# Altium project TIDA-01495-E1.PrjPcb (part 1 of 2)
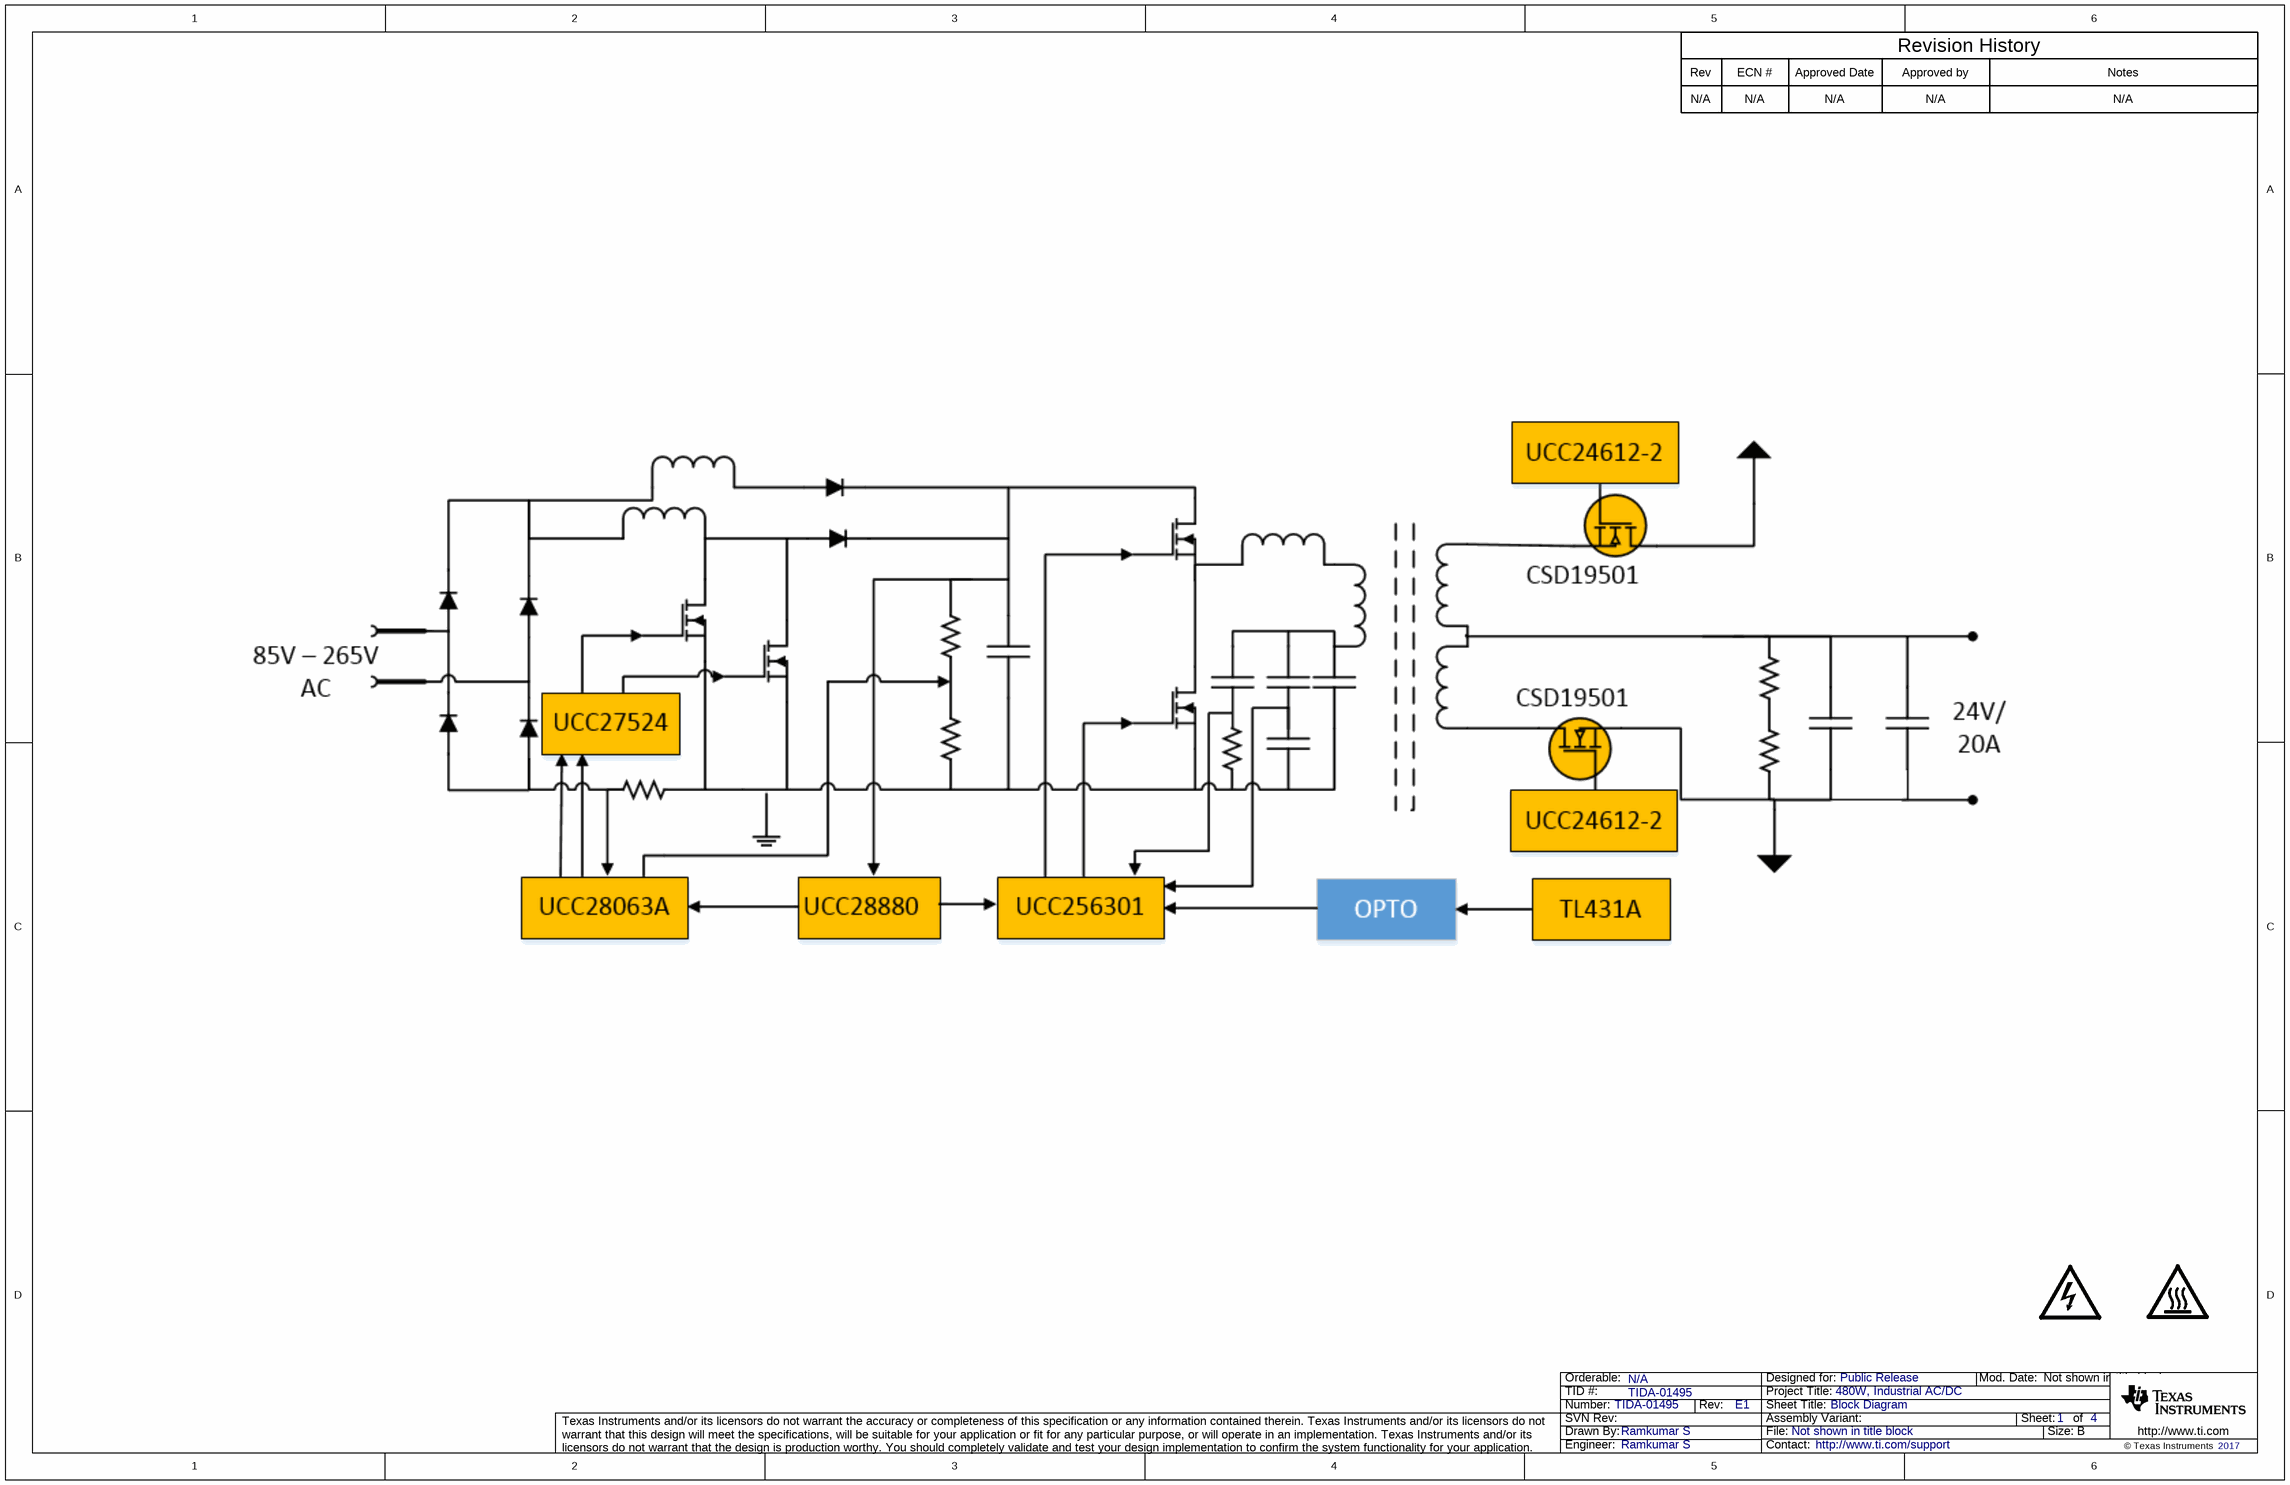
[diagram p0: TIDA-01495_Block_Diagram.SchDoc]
CopyrightYear: 2017; EVM_orderable: N/A; PCB_Layout: Akshay Labhe; PCB_Rev: E1; PRJ_Customer: Public Release; PRJ_Engineer: Ramkumar S; PRJ_Number: TIDA-01495; PRJ_Title: 480W, Industrial AC/DC; SCH_Rev: E1; TechSupport: http://www.ti.com/support; TID: TIDA-01495
4 sheets, 249 parts. Net scope: global (net labels, ports and power ports of the same name join across sheets).
Board file: TIDA-01495_PCB.PcbDoc
Sheets:
  TIDA-01495_Block_Diagram.SchDoc
  TIDA-01495_PFC.SchDoc
  TIDA-01495-LLC.SchDoc
  TIDA-01495_Hardware.SchDoc

## Sheet TIDA-01495_Block_Diagram.SchDoc: Block Diagram
size 431 x 279 mm; Date: Not shown in title block; ApprovedBy: Not shown in title block; CheckedBy: Not shown in title block; Author: Not shown in title block; CompanyName: Not shown in title block; DrawnBy: Ramkumar S; Engineer: Ramkumar S; Organization: Not shown in title block; Address1: Not shown in title block; Address2: Not shown in title block; Address3: Not shown in title block; Address4: Not shown in title block; DocumentNumber: 1; Revision: Use project parameter SCH_Rev; SheetNumber: 1; SheetTotal: 4; PageSetup: Record=PageOptions¦CenterHorizontal=True¦CenterVertical=True¦PrintScale=1.00¦XCorrection=1.00¦YCorrection=1.00¦PrintKind=0¦BorderSize=5000000¦LeftOffset=0¦BottomOffset=0¦Orientation=2¦PaperLength=1000¦PaperWidth=1000¦Scale=100¦PaperSource=15¦PrintQuality=600¦MediaType=1¦DitherType=10¦PaperKind=Letter¦PrintScaleMode=1

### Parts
(Parts that share a designator on the sheet are numbered #1, #2 ... from top to bottom, then left to right.)
LOGO?#1  DANGER HIGH VOLTAGE  [IEC_HighVoltage_Small]  (value not drawn)  (graphical)
LOGO?#2  CAUTION HOT SURFACE  [IEC_HotSurface_Small]  (value not drawn)  (graphical)

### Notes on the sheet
- Rev
- N/A
- ECN #
- Approved Date
- Approved by
- Revision History
- Notes

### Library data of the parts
LOGO?#1 = IEC_HighVoltage: IEC 61010-1 High Voltage Warning; SymbolCreator: a0412235
LOGO?#2 = IEC_HotSurface: IEC 61010-1 Hot Surface Warning; SymbolCreator: a0412235

## Sheet TIDA-01495_PFC.SchDoc: PFC
size 431 x 279 mm; Date: Not shown in title block; ApprovedBy: Not shown in title block; CheckedBy: Not shown in title block; Author: Not shown in title block; CompanyName: Not shown in title block; DrawnBy: Ramkumar S; Engineer: Ramkumar S; Organization: Not shown in title block; Address1: Not shown in title block; Address2: Not shown in title block; Address3: Not shown in title block; Address4: Not shown in title block; DocumentNumber: 1; Revision: Use project parameter SCH_Rev; SheetNumber: 2; SheetTotal: 4; PageSetup: Record=PageOptions¦CenterHorizontal=True¦CenterVertical=True¦PrintScale=1.00¦XCorrection=1.00¦YCorrection=1.00¦PrintKind=0¦BorderSize=5000000¦LeftOffset=0¦BottomOffset=0¦Orientation=2¦PaperLength=1000¦PaperWidth=1000¦Scale=100¦PaperSource=15¦PrintQuality=600¦MediaType=1¦DitherType=10¦PaperKind=Letter¦PrintScaleMode=1
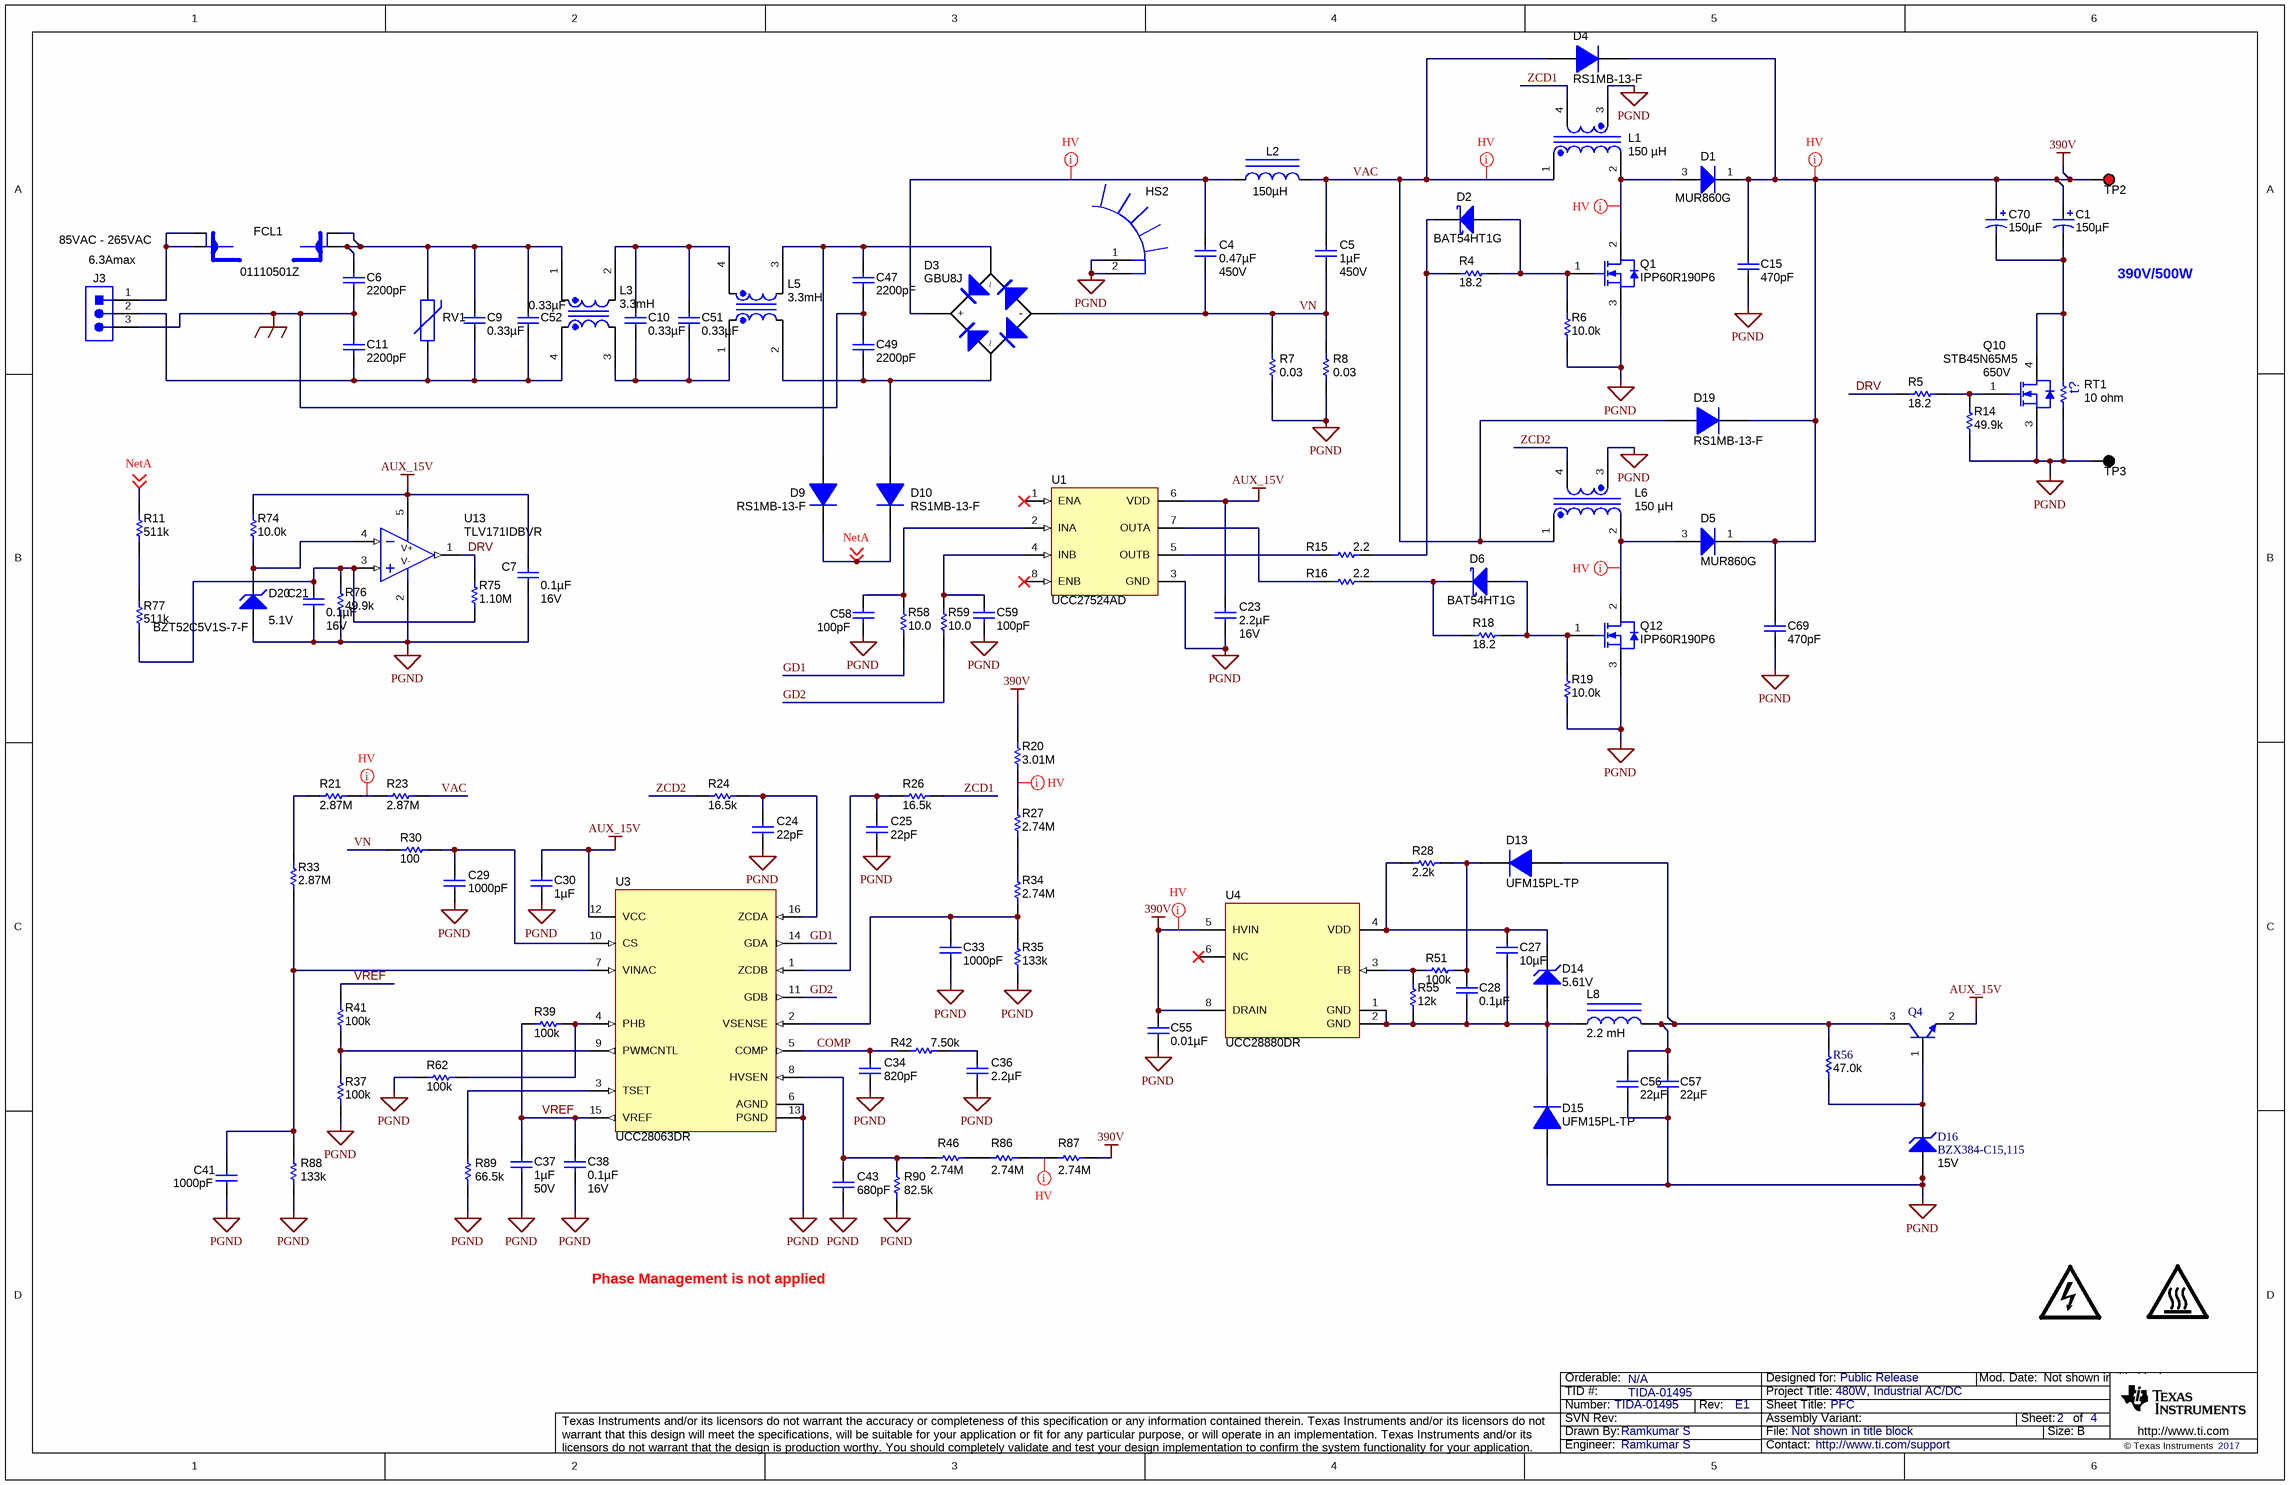
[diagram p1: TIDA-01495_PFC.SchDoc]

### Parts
(Parts that share a designator on the sheet are numbered #1, #2 ... from top to bottom, then left to right.)
C1  ValueDisplayed: 150µF  [KXG_1800x4000_horizontalDown]  (hidden comment: 450BXW150MEFC18X45)
C4  ValueDisplayed: 0.47µF  Value2: 450V  [MPK_1800x650]  (hidden comment: 450MPK474J)
C5  ValueDisplayed: 1µF  Value2: 450V  [MPK_1800x950]  (hidden comment: 450MPK105J)
C6  ValueDisplayed: 2200pF  [CD45_700x600x1100]  (hidden comment: AY2222M35Y5US63L7)
C7  ValueDisplayed: 0.1µF  Value2: 16V  [0603]  (hidden comment: EMK107B7104KA-T)
C9  ValueDisplayed: 0.33µF  [B32922_14.5mm]  (hidden comment: B32922C3334K)
C10  ValueDisplayed: 0.33µF  [B32922_14.5mm]  (hidden comment: B32922C3334K)
C11  ValueDisplayed: 2200pF  [CD45_700x600x1100]  (hidden comment: AY2222M35Y5US63L7)
C15  ValueDisplayed: 470pF  [1210]  (hidden comment: VJ1210Y471KXEAT5Z)
C21  ValueDisplayed: 0.1µF  Value2: 16V  [0603]  (hidden comment: EMK107B7104KA-T)
C23  ValueDisplayed: 2.2µF  Value2: 16V  [0805_HV]  (hidden comment: 0805YD225KAT2A)
C24  ValueDisplayed: 22pF  [0603]  (hidden comment: C0603C220J5GACTU)
C25  ValueDisplayed: 22pF  [0603]  (hidden comment: C0603C220J5GACTU)
C27  ValueDisplayed: 10µF  [0603]  (hidden comment: C1608X5R1A106M)
C28  ValueDisplayed: 0.1µF  [0603]  (hidden comment: 0603YC104JAT2A)
C29  ValueDisplayed: 1000pF  [0603]  (hidden comment: C1608X7R1H102K)
C30  ValueDisplayed: 1µF  [0603]  (hidden comment: GRM188R71E105KA12D)
C33  ValueDisplayed: 1000pF  [0603]  (hidden comment: C1608X7R1H102K)
C34  ValueDisplayed: 820pF  [0603]  (hidden comment: 06035A821JAT2A)
C36  ValueDisplayed: 2.2µF  [0805_HV]  (hidden comment: 0805YD225KAT2A)
C37  ValueDisplayed: 1µF  Value2: 50V  [0603]  (hidden comment: UMK107AB7105KA-T)
C38  ValueDisplayed: 0.1µF  Value2: 16V  [0603]  (hidden comment: EMK107B7104KA-T)
C41  ValueDisplayed: 1000pF  [0603]  (hidden comment: 06031C102MAT2A)
C43  ValueDisplayed: 680pF  [0603]  (hidden comment: GRM188R71H681KA01D)
C47  ValueDisplayed: 2200pF  [CAPRD500W60D800H850]  (hidden comment: DE2E3KY222MA2BM01)
C49  ValueDisplayed: 2200pF  [CAPRD500W60D800H850]  (hidden comment: DE2E3KY222MA2BM01)
C51  ValueDisplayed: 0.33µF  [B32922_14.5mm]  (hidden comment: B32922C3334K)
C52  ValueDisplayed: 0.33µF  [B32922_14.5mm]  (hidden comment: B32922C3334K)
C55  ValueDisplayed: 0.01µF  [1808]  (hidden comment: VJ1808Y103KBLAT4X)
C56  ValueDisplayed: 22µF  [1206_180]  (hidden comment: C3216X5R1V226M160AC)
C57  ValueDisplayed: 22µF  [1206_180]  (hidden comment: C3216X5R1V226M160AC)
C58  ValueDisplayed: 100pF  [0805_HV1]  (hidden comment: 08055A101JAT2A)
C59  ValueDisplayed: 100pF  [0805_HV1]  (hidden comment: 08055A101JAT2A)
C69  ValueDisplayed: 470pF  [1210]  (hidden comment: VJ1210Y471KXEAT5Z)
C70  ValueDisplayed: 150µF  [KXG_1800x4000_horizontalDown]  (hidden comment: 450BXW150MEFC18X45)
D1  MUR860G  [TO-220AC_HORIZ]
D2  BAT54HT1G  [sod-323]
D3  GBU8J  [GBU]
D4  RS1MB-13-F  [SMB]
D5  MUR860G  [TO-220AC_HORIZ]
D6  BAT54HT1G  [sod-323]
D9  RS1MB-13-F  [SMB]
D10  RS1MB-13-F  [SMB]
D13  UFM15PL-TP  [SOD-123FL]
D14  5.61V  [SOD-523]
D15  UFM15PL-TP  [SOD-123FL]
D16  BZX384-C15,115  value 15V  [sod-323]
D19  RS1MB-13-F  [SMB]
D20  BZT52C5V1S-7-F  value 5.1V  [SOD-323]
FCL1  01110501Z  [LITTELFUSE_01110501Z]
HS2  (no value)  [HEATSINK_782653B04250G - duplicate1]
J3  350429-1  [TE_350429-1]  (value not drawn)
L1  value 150 µH  [WE-CMBH_Updated]  (hidden comment: Custom)
L2  ValueDisplayed: 150µH  [IND_7447020]  (hidden comment: 7447076)
L3  ValueDisplayed: 3.3mH  [WE-CMBH]  (hidden comment: 744834433)
L5  ValueDisplayed: 3.3mH  [WE-CMBH]  (hidden comment: 744834433)
L6  value 150 µH  [WE-CMBH_Updated]  (hidden comment: Custom)
L8  ValueDisplayed: 2.2 mH  [WE-TI_5075]  (hidden comment: 744741222)
LOGO?#3  DANGER HIGH VOLTAGE  [IEC_HighVoltage_Small]  (value not drawn)  (graphical)
LOGO?#4  CAUTION HOT SURFACE  [IEC_HotSurface_Small]  (value not drawn)  (graphical)
Q1  IPP60R190P6  [TO-220AB_HORIZONTAL]
Q4  BC848CLT1G  [SOT-23]  (value not drawn)
Q10  STB45N65M5  value 650V  [DDPAK]
Q12  IPP60R190P6  [TO-220AB_HORIZONTAL]
R4  ValueDisplayed: 18.2  [0805_HV1]  (hidden comment: CRCW080518R2FKEA)
R5  ValueDisplayed: 18.2  [0805_HV1]  (hidden comment: CRCW080518R2FKEA)
R6  ValueDisplayed: 10.0k  [0805_HV]  (hidden comment: CRCW080510K0FKEA)
R7  ValueDisplayed: 0.03  [2512]  (hidden comment: CSRN2512FK30L0)
R8  ValueDisplayed: 0.03  [2512]  (hidden comment: CSRN2512FK30L0)
R11  value 511k  [1206]  (hidden comment: CRCW1206511KFKEA)
R14  value 49.9k  [1206]  (hidden comment: CRCW120649K9FKEA)
R15  ValueDisplayed: 2.2  [0805_HV1]  (hidden comment: CRCW08052R20JNEA)
R16  ValueDisplayed: 2.2  [0805_HV1]  (hidden comment: CRCW08052R20JNEA)
R18  ValueDisplayed: 18.2  [0805_HV1]  (hidden comment: CRCW080518R2FKEA)
R19  ValueDisplayed: 10.0k  [0805_HV]  (hidden comment: CRCW080510K0FKEA)
R20  ValueDisplayed: 3.01M  [0805_HV]  (hidden comment: CRCW08053M01FKEA)
R21  ValueDisplayed: 2.87M  [0805_HV]  (hidden comment: CRCW08052M87FKEA)
R23  ValueDisplayed: 2.87M  [0805_HV]  (hidden comment: CRCW08052M87FKEA)
R24  ValueDisplayed: 16.5k  [0603]  (hidden comment: CRCW060316K5FKEA)
R26  ValueDisplayed: 16.5k  [0603]  (hidden comment: CRCW060316K5FKEA)
R27  ValueDisplayed: 2.74M  [0805_HV]  (hidden comment: CRCW08052M74FKEA)
R28  ValueDisplayed: 2.2k  [0603]  (hidden comment: CRCW06032K20JNEA)
R30  ValueDisplayed: 100  [0603]  (hidden comment: CRCW0603100RFKEA)
R33  ValueDisplayed: 2.87M  [0805_HV]  (hidden comment: CRCW08052M87FKEA)
R34  ValueDisplayed: 2.74M  [0805_HV]  (hidden comment: CRCW08052M74FKEA)
R35  ValueDisplayed: 133k  [0603]  (hidden comment: CRCW0603133KFKEA)
R37  ValueDisplayed: 100k  [0603]  (hidden comment: CRCW0603100KJNEA)
R39  ValueDisplayed: 100k  [0603]  (hidden comment: CRCW0603100KJNEA)
R41  ValueDisplayed: 100k  [0603]  (hidden comment: CRCW0603100KJNEA)
R42  ValueDisplayed: 7.50k  [0603]  (hidden comment: CRCW06037K50FKEA)
R46  ValueDisplayed: 2.74M  [0805_HV]  (hidden comment: CRCW08052M74FKEA)
R51  ValueDisplayed: 100k  [0603]  (hidden comment: CRCW0603100KJNEA)
R55  ValueDisplayed: 12k  [0603]  (hidden comment: CRCW060312K0JNEA)
R56  ValueDisplayed: 47.0k  [0603]  (hidden comment: RT0603BRD0747KL)
R58  ValueDisplayed: 10.0  [0603]  (hidden comment: CRCW060310R0FKEAHP)
R59  ValueDisplayed: 10.0  [0603]  (hidden comment: CRCW060310R0FKEAHP)
R62  ValueDisplayed: 100k  [0603]  (hidden comment: CRCW0603100KJNEA)
R74  ValueDisplayed: 10.0k  [0805_HV]  (hidden comment: CRCW080510K0FKEA)
R75  ValueDisplayed: 1.10M  [0603]  (hidden comment: CRCW06031M10FKEA)
R76  value 49.9k  [1206]  (hidden comment: CRCW120649K9FKEA)
R77  value 511k  [1206]  (hidden comment: CRCW1206511KFKEA)
R86  ValueDisplayed: 2.74M  [0805_HV]  (hidden comment: CRCW08052M74FKEA)
R87  ValueDisplayed: 2.74M  [0805_HV]  (hidden comment: CRCW08052M74FKEA)
R88  ValueDisplayed: 133k  [0603]  (hidden comment: CRCW0603133KFKEA)
R89  ValueDisplayed: 66.5k  [0603]  (hidden comment: CRCW060366K5FKEA)
R90  ValueDisplayed: 82.5k  [0603]  (hidden comment: CRCW060382K5FKEA)
RT1  value 10 ohm  [THERM_B57236S0]  (hidden comment: B57236S0100M000)
RV1  S10K275E2  [VAR_S10K275E2]  (value not drawn)
TP2  5000  [Keystone5000]  (value not drawn)
TP3  5001  [Keystone5001]  (value not drawn)
U1  UCC27524AD  [D0008A_N]
U3  UCC28063DR  [D0016A_N]
U4  UCC28880DR  [D0007A_N]
U13  TLV171IDBVR  [DBV0005A_N]

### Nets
390V: C1.1(+) C15.1 C55.1 C69.1 C70.1(+) D1.1(K) D4.1(K) D5.1(K) D19.1(K) R20.2 R87.2 TP2.1 U4.5(HVIN) U4.8(DRAIN)
AUX_15V: C7.1 C23.1 C30.1 Q4.2(E) R74.2 U1.6(VDD) U3.12(VCC) U13.5(V+)
EARTH: C6.2 C11.1 C47.2 C49.1 J3.3
PGND: C7.2 C15.2 C21.2 C23.2 C24.2 C25.2 C29.2 C30.2 C33.2 C34.2 C36.2 C37.2 C38.2 C41.2 C43.2 C55.2 C56.2 C57.2 C58.2 C59.2 C69.2 D15.2(A) D16.2(A) D20.2(A) HS2.1 HS2.2 L1.3 L6.3 Q1.3(S) Q10.3(S) Q12.3(S) R6.1 R7.1 R8.1 R14.1 R19.1 R35.1 R37.2 R62.1 R76.1 R88.1 R89.1 R90.1 RT1.1 TP3.1 U1.3(GND) U3.6(AGND) U3.13(PGND) U13.2(V-)
COMP: C34.1 R42.1 U3.5(COMP)
DRV: R5.2 R75.2 U13.1(OUT)
GD1: R58.1 U3.14(GDA)
GD2: R59.1 U3.11(GDB)
NetA: D9.1(K) D10.1(K) R11.1 ; off-sheet NetA
VAC: C5.2 D4.2(A) D19.2(A) L1.1 L2.2 L6.1 R23.2
VN: C4.2 C5.1 D3.4(-) R7.2 R8.2 R30.1
VREF: C37.1 C38.1 R39.1 R41.2 U3.15(VREF)
ZCD1: L1.4 R26.2
ZCD2: L6.4 R24.1
NetC1_2: C1.2(-) C70.2(-) Q10.4(D) RT1.2
NetC4_1: C4.1 D3.1(+) L2.1
NetC6_1: C6.1 C9.1 C52.1 FCL1.3 FCL1.4 L3.1 RV1.2
NetC9_2: C9.2 C11.2 C52.2 J3.2 L3.4 RV1.1
NetC10_1: C10.1 C51.1 L3.2 L5.4
NetC10_2: C10.2 C51.2 L3.3 L5.1
NetC21_1: C21.1 R75.1 R76.2 R77.2 U13.3(IN+)
NetC24_1: C24.1 R24.2 U3.16(ZCDA)
NetC25_1: C25.1 R26.1 U3.1(ZCDB)
NetC27_1: C27.1 D14.1(K) R28.1 U4.4(VDD)
NetC27_2: C27.2 C28.2 D14.2(A) D15.1(K) L8.1 R55.1 U4.1(GND) U4.2(GND)
NetC28_1: C28.1 D13.1(K) R28.2 R51.1
NetC29_1: C29.1 R30.2 U3.10(CS)
NetC33_1: C33.1 R34.1 R35.2 U3.2(VSENSE)
NetC36_1: C36.1 R42.2
NetC41_1: C41.1 R33.1 R88.2 U3.7(VINAC)
NetC43_1: C43.1 R46.1 R90.2 U3.8(HVSEN)
NetC47_1: C47.1 D3.2 D9.2(A) L5.3
NetC49_2: C49.2 D3.3 D10.2(A) L5.2
NetC56_1: C56.1 C57.1 D13.2(A) L8.2 Q4.3(C) R56.2
NetC58_1: C58.1 R58.2 U1.2(INA)
NetC59_1: C59.1 R59.2 U1.4(INB)
NetD1_3: D1.3(A) L1.2 Q1.2(D)
NetD2_1: D2.1(K) R4.1 R15.2
NetD2_2: D2.2(A) Q1.1(G) R4.2 R6.2
NetD5_3: D5.3(A) L6.2 Q12.2(D)
NetD6_1: D6.1(K) R16.2 R18.1
NetD6_2: D6.2(A) Q12.1(G) R18.2 R19.2
NetD16_1: D16.1(K) Q4.1(B) R56.1
NetD20_1: D20.1(K) R74.1 U13.4(IN-)
NetFCL1_1: FCL1.1 FCL1.2 J3.1
NetQ10_1: Q10.1(G) R5.1 R14.2
NetR11_2: R11.2 R77.1
NetR15_1: R15.1 U1.5(OUTB)
NetR16_1: R16.1 U1.7(OUTA)
NetR20_1: R20.1 R27.2
NetR21_1: R21.1 R33.2
NetR21_2: R21.2 R23.1
NetR27_1: R27.1 R34.2
NetR37_1: R37.1 R41.1 U3.9(PWMCNTL)
NetR39_2: R39.2 R62.2 U3.4(PHB)
NetR46_2: R46.2 R86.1
NetR51_2: R51.2 R55.2 U4.3(FB)
NetR86_2: R86.2 R87.1
NetR89_2: R89.2 U3.3(TSET)

Not connected (* = marked no-connect by the designer): U1 1(ENA)* 8(ENB)*; U4 6(NC)*

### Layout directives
net class HV: 390V, NetC4_1, NetD1_3, NetD5_3, NetR20_1, NetR21_2, NetR86_2, VAC

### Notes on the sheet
- 85VAC - 265VAC
- (near J3) 6.3Amax
- 390V/500W
- Phase Management is not applied

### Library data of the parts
C1 C70 = 450BXW150MEFC18X45: CAP, AL, 150 µF, 450 V, +/- 20%, TH; Manufacturer: Rubycon; Polarized: Y; CompType: Capacitor; Value: 150uF; U/M: EA; Cap_F: 0.00015; Tolerance_%: 20; VDC_V: 450; Value2: 450V; IRMS_A: 1; TaMin_C: -40; TaMax_C: 105; Cap_Case: 18x45mm; SizeAreaWB_mm2: 400; SizeArea_mm2: 324; SizeX_mm: 18; SizeZ_mm: 47; AEC Category: Q200; AEC Qualified: N; Green_Lifecycle: Not Set; Green_REACh: Incomplete
C4 = 450MPK474J: CAP, Film, 0.47 µF, 450 V, +/- 5%, TH; Manufacturer: Rubycon; Polarized: N; CompType: Capacitor; Value: 0.47uF; U/M: EA; Cap_F: 0.00000047; Tolerance_%: 5; Value1: Unknown; VDC_V: 450; TaMin_C: -40; TaMax_C: 105; Cap_Case: 18x6.5mm; AEC Category: Q200
C5 = 450MPK105J: CAP, Film, 1 µF, 450 V, +/- 5%, TH; Manufacturer: Rubycon; Polarized: N; CompType: Capacitor; Value: 1uF; U/M: EA; Cap_F: 0.000001; Tolerance_%: 5; Value1: Unknown; VDC_V: 450; TaMin_C: -40; TaMax_C: 105; Cap_Case: 18x9.5mm
C6 C11 = AY2222M35Y5US63L7: CAP, CERM, 2200 pF, 300 V, +/- 20%, Y5U, AEC-Q200 Grade 1, D9.5xT5mm; Manufacturer: Vishay-Bccomponents; Polarized: N; CompType: Capacitor; Value: 2200pF; U/M: EA; Cap_F: 0.0000000022; Tolerance_%: 20; Value1: Unknown; VDC_V: 300; Value2: 300V; TaMin_C: -55; TaMax_C: 125; Cap_Case: 9.5x5mm; SizeArea_mm2: 47.5; SizeAreaWB_mm2: 80.5; SizeX_mm: 9.5; SizeY_mm: 5; SizeZ_mm: 14.5; AEC Category: Q200; AEC Qualified: Y; AEC Grade: 1
C7 C21 C38 = EMK107B7104KA-T: CAP, CERM, 0.1 µF, 16 V, +/- 10%, X7R, 0603; Manufacturer: Taiyo Yuden; Polarized: N; CompType: Capacitor; Value: 0.1uF; U/M: EA; Cap_F: 0.0000001; Tolerance_%: 10; Value1: Unknown; VDC_V: 16; TaMin_C: -55; TaMax_C: 125
C9 C10 C51 C52 = B32922C3334K: CAP, Film, 0.33 µF, X2 305 VAC, +/- 10%, TH; Manufacturer: TDK; Polarized: N; CompType: Capacitor; Value: 0.33uF; U/M: EA; Cap_F: 0.00000033; Tolerance_%: 10; TaMin_C: -40; TaMax_C: 110; Cap_Case: 18x8x14.5mm; SizeAreaWB_mm2: 210; SizeArea_mm2: 153; SizeX_mm: 18; SizeY_mm: 8.5; SizeZ_mm: 14.5; AEC Category: Q200; VAC_X: 305
C15 C69 = VJ1210Y471KXEAT5Z: CAP, CERM, 470 pF, 500 V, +/- 10%, X7R, 1210; Manufacturer: Vishay-Vitramon; Polarized: N; CompType: Capacitor; Value: 470pF; U/M: EA; Cap_F: 0.00000000047; Tolerance_%: 10; Value1: Unknown; VDC_V: 500; Value2: 500V; TaMin_C: -55; TaMax_C: 125; SizeArea_mm2: 8; SizeAreaWB_mm2: 14.7; SizeX_mm: 3.2; SizeY_mm: 2.5; SizeZ_mm: 1.35; AEC Category: Q200
C23 = 0805YD225KAT2A: CAP, CERM, 2.2 µF, 16 V, +/- 10%, X5R, 0805; Manufacturer: AVX; Polarized: N; CompType: Capacitor; Value: 2.2uF; U/M: EA; Cap_F: 0.0000022; Tolerance_%: 10; ESR_ohm: 0.009; Value1: 0.009 ohm; VDC_V: 16; TaMin_C: -55; TaMax_C: 85; Cap_Case: 0805
C24 C25 = C0603C220J5GACTU: CAP, CERM, 22 pF, 50 V, +/- 5%, C0G/NP0, 0603; Manufacturer: Kemet; Polarized: N; CompType: Capacitor; Value: 22pF; U/M: EA; Cap_F: 0.000000000022; Tolerance_%: 5; Value1: Unknown; VDC_V: 50; Value2: 50V; TaMin_C: -55; TaMax_C: 125
C27 = C1608X5R1A106M: CAP, CERM, 10 µF, 10 V, +/- 20%, X5R, 0603; Manufacturer: TDK; Polarized: N; CompType: Capacitor; Value: 10uF; U/M: EA; Cap_F: 0.00001; Tolerance_%: 20; ESR_ohm: 0.0078; Value1: 0.0078 ohm; VDC_V: 10; Value2: 10V; IRMS_A: 1.85; TaMin_C: -55; TaMax_C: 85
C28 = 0603YC104JAT2A: CAP, CERM, 0.1 µF, 16 V, +/- 5%, X7R, 0603; Manufacturer: AVX; Polarized: N; CompType: Capacitor; Value: 0.1uF; U/M: EA; Cap_F: 0.0000001; Tolerance_%: 5; ESR_ohm: 0.039; Value1: 0.039 ohm; VDC_V: 16; Value2: 16V; TaMin_C: -55; TaMax_C: 125
C29 C33 = C1608X7R1H102K: CAP, CERM, 1000 pF, 50 V, +/- 10%, X7R, 0603; Manufacturer: TDK; Polarized: N; CompType: Capacitor; Value: 1000pF; U/M: EA; Cap_F: 0.000000001; Tolerance_%: 10; ESR_ohm: 0.24; Value1: 0.24 ohm; VDC_V: 50; Value2: 50V; TaMin_C: -55; TaMax_C: 125
C30 = GRM188R71E105KA12D: CAP, CERM, 1 µF, 25 V, +/- 10%, X7R, 0603; Manufacturer: MuRata; Polarized: N; CompType: Capacitor; Value: 1uF; U/M: EA; Cap_F: 0.000001; Tolerance_%: 10; Value1: Unknown; VDC_V: 25; Value2: 25V; TaMin_C: -55; TaMax_C: 125
C34 = 06035A821JAT2A: CAP, CERM, 820 pF, 50 V, +/- 5%, C0G/NP0, 0603; Manufacturer: AVX; Polarized: N; CompType: Capacitor; Value: 820pF; U/M: EA; Cap_F: 0.00000000082; Tolerance_%: 5; ESR_ohm: 0.052; Value1: 0.052 ohm; VDC_V: 50; Value2: 50V; TaMin_C: -55; TaMax_C: 125
C36 = 0805YD225KAT2A: CAP, CERM, 2.2 µF, 16 V, +/- 10%, X5R, 0805; Manufacturer: AVX; Polarized: N; CompType: Capacitor; Value: 2.2uF; U/M: EA; Cap_F: 0.0000022; Tolerance_%: 10; ESR_ohm: 0.009; Value1: 0.009 ohm; VDC_V: 16; Value2: 16V; TaMin_C: -55; TaMax_C: 85; Cap_Case: 0805
C37 = UMK107AB7105KA-T: CAP, CERM, 1 µF, 50 V, +/- 10%, X7R, 0603; Manufacturer: Taiyo Yuden; Polarized: N; CompType: Capacitor; Value: 1uF; U/M: EA; Cap_F: 0.000001; Tolerance_%: 10; Value1: Unknown; VDC_V: 50; TaMin_C: -55; TaMax_C: 125
C41 = 06031C102MAT2A: CAP, CERM, 1000 pF, 100 V, +/- 20%, X7R, 0603; Manufacturer: AVX; Polarized: N; CompType: Capacitor; Value: 1000pF; U/M: EA; Cap_F: 0.000000001; Tolerance_%: 20; ESR_ohm: 0.276; Value1: 0.276 ohm; VDC_V: 100; Value2: 100V; TaMin_C: -55; TaMax_C: 125
C43 = GRM188R71H681KA01D: CAP, CERM, 680 pF, 50 V, +/- 10%, X7R, 0603; Manufacturer: MuRata; Polarized: N; CompType: Capacitor; Value: 680pF; U/M: EA; Cap_F: 0.00000000068; Tolerance_%: 10; Value1: Unknown; VDC_V: 50; Value2: 50V; TaMin_C: -55; TaMax_C: 125
C47 C49 = DE2E3KY222MA2BM01: CAP, CERM, 2200 pF, X1 250 VAC/Y2 300 VAC, +/- 20%, E, Radial D8x5mm; Manufacturer: MuRata; Polarized: N; CompType: Capacitor; Value: 2200pF; U/M: EA; Cap_F: 0.0000000022; Tolerance_%: 20; TaMin_C: -25; TaMax_C: 85; SizeArea_mm2: 40; SizeAreaWB_mm2: 70; SizeX_mm: 8; SizeY_mm: 5; SizeZ_mm: 11; AEC Category: Q200; Green_Lifecycle: Not Set; Green_REACh: Incomplete; AC_Safety: X1Y2; VAC_X: 250; VAC_Y: 300
C55 = VJ1808Y103KBLAT4X: CAP, CERM, 0.01 µF, 630 V,+/- 10%, X7R, 1808; Manufacturer: Vishay-Vitramon; Polarized: N; CompType: Capacitor; Value: 0.01uF; U/M: EA; Cap_F: 0.00000001; Tolerance_%: 10; VDC_V: 630; Value2: 630V; TaMin_C: -55; TaMax_C: 125; SizeArea_mm2: 9; SizeAreaWB_mm2: 16.5; SizeX_mm: 4.5; SizeY_mm: 2; SizeZ_mm: 2.03; AEC Category: Q200
C56 C57 = C3216X5R1V226M160AC: CAP, CERM, 22 µF, 35 V,+/- 20%, X5R, 1206; Manufacturer: TDK; Polarized: N; CompType: Capacitor; Value: 22uF; U/M: EA; Cap_F: 0.000022; Tolerance_%: 20; ESR_ohm: 0.002398; Value1: 0.002398 ohm; VDC_V: 35; Value2: 35V; IRMS_A: 4.68507; TaMin_C: -55; TaMax_C: 85; Cap_Case: 1206; SizeArea_mm2: 5.12; SizeAreaWB_mm2: 10.92; SizeX_mm: 3.2; SizeY_mm: 1.6; SizeZ_mm: 1.8; AEC Category: Q200; Green_Lifecycle: Active; Green_REACh: Passed
C58 C59 = 08055A101JAT2A: CAP, CERM, 100 pF, 50 V,+/- 5%, C0G/NP0, 0805; Manufacturer: AVX; Polarized: N; CompType: Capacitor; Value: 100pF; U/M: EA; Cap_F: 0.0000000001; Tolerance_%: 5; ESR_ohm: 0.356; Value1: 0.356 ohm; VDC_V: 50; Value2: 50V; TaMin_C: -55; TaMax_C: 125; Cap_Case: 0805; SizeArea_mm2: 2.5; SizeAreaWB_mm2: 6.75; SizeX_mm: 2; SizeY_mm: 1.25; SizeZ_mm: 1.45; AEC Category: Q200; Green_Lifecycle: Active; Green_REACh: Passed
D1 D5 = MUR860G: Diode, Ultrafast, 600V, 8A, TH; Manufacturer: ON Semiconductor; SymbolCreator: a0412235; Value: 0.98V; U/M: EA; Vf_V: 0.98; Io_A: 8; Vr_V: 600; TJmax_C: 175; RJC_CperW: 4.75
D2 D6 = BAT54HT1G: Diode, Schottky, 30V, 0.2A, SOD-323; Manufacturer: ON Semiconductor; Value: 0.35V; U/M: EA; Vf_V: 0.35; Io_A: 0.2; Vr_V: 30
D3 = GBU4A-BP: DIODE GPP 8A 600V GPP INLINE GBU; Manufacturer: Vishay; U/M: EA; Vf_V: 0.95; Io_A: 4; Value1: 4A; Vr_V: 50; Value2: 50V; TJmax_C: 150; RJC_CperW: 2.2; Type: Switching-Bridge
D4 D19 = CMP-0076889-1: Diode, P-N, 1000 V, 1 A, SMB; Manufacturer: Diodes Inc.; SizeAreaWB_mm2: 44.156; Vr_V: 1kV; SizeArea_mm2: 21.336; TJmax_C: 150°C; AEC Category: Q101; Value: 1000V; SizeZ_mm: 2.6; Green_REACh: Passed; Io_A: 1A; Vf_V: 1.3V; SizeY_mm: 3.81; Green_Lifecycle: Active; U/M: EA; SizeX_mm: 5.6; RJC_CperW: 20.0
D9 D10 = RS1MB-13-F: Diode, P-N, 1000 V, 1 A, SMB; Manufacturer: Diodes Inc.; U/M: EA; Vf_V: 1.3; Value: 1000V; Value1: 1A; Value2: 1.3V; Io_A: 1; Vr_V: 1000; TJmax_C: 150; RJC_CperW: 20; SizeAreaWB_mm2: 44.156; SizeArea_mm2: 21.336; SizeX_mm: 5.6; SizeY_mm: 3.81; SizeZ_mm: 2.6; AEC Category: Q101; Green_Lifecycle: Active; Green_REACh: Passed
D13 D15 = UFM15PL-TP: Diode, Ultrafast, 600 V, 1 A, SOD-123FL; Manufacturer: Micro Commercial Components; U/M: EA; Vf_V: 1.7; Value: 600V; Value1: 1A; Value2: 1.7V; Io_A: 1; Vr_V: 600; TJmax_C: 150; SizeAreaWB_mm2: 12.19; SizeArea_mm2: 5.94; SizeX_mm: 3.6; SizeY_mm: 1.65; SizeZ_mm: 0.98; AEC Category: Q101; AEC Qualified: N; Green_Lifecycle: Not Set; Green_REACh: Incomplete
D14 = MM5Z5V6ST1G: Diode, Zener, 5.61 V, 500 mW, SOD-523; Manufacturer: ON Semiconductor; SymbolCreator: a0412235; U/M: EA; Power_W: 0.5; Vz_V: 5.61; Value1: 0.5W; RJA_CperW: 250
D16 = BZX384-C15,115: Diode, Zener, 15 V, 300 mW, SOD-323; Manufacturer: NXP Semiconductor; SymbolCreator: a0412235; U/M: EA; Power_W: 0.3; Vz_V: 15; Value1: 0.3W; RJA_CperW: 415
D20 = CMP-0005865-1: Diode, Zener, 5.1 V, 200 mW, SOD-323; Manufacturer: Diodes Inc.; Power_W: 200mW; SizeAreaWB_mm2: 8.695; Value1: 0.2W; RJA_CperW: 625; U/M: EA; SizeZ_mm: 1; SizeX_mm: 2.7; SizeY_mm: 1.35; SizeArea_mm2: 3.645; AEC Category: Q101
FCL1 = 01110501Z: FUSE CLIP, CARTRIDGE, 250V, 10A, PCB; Manufacturer: LITTELFUSE; SymbolCreator: x0199378
HS2 = ATS-TI1OP-519-C1-R3: Heat Sink, Vertical; Manufacturer: Advanced Thermal Solutions; SymbolCreator: a0799628; Green_Lifecycle: Not Set; Green_REACh: Incomplete
J3 = 350429-1: Header(Shrouded), 6.35mm, 3x1, Tin, TH; Manufacturer: TE Connectivity; SymbolCreator: a0799628; U/M: EA
L1 L6 = PFC4124QM-161K06D-00: Transformer, 160 uH, TH; SymbolCreator: Altium; U/M: EA
L2 = 7447020: Inductor, Toroid, Powdered Iron, 150 µH, 5A, TH; Manufacturer: Wurth Elektronik; Value: 150uH; Value1: 0.16 ohm
L3 L5 = 744834433: Coupled inductor, 3.3 mH, 5 A, 0.037 ohm, TH; Manufacturer: Wurth Elektronik; SymbolCreator: a0412235; Value: 3.3mH; Ind_H: 3.3E-3; DCR_ohm: 0.037; AEC Category: Q200
L8 = 7447462102: FIXED IND 2.2MH 210MA 11 OHM TH; Manufacturer: Wurth Elektronik; CompType: Inductor; Value: 1mH; Ind_H: 1.0E-3; Irms: 0.25A @ 40C rise; Isat: 0.27A @ 10% inductance drop; DCR_ohm: 4.38; Value1: 4.38 ohm; Value2: 0.25A; Material: Ferrite; SizeAreaWB_mm2: 64; SizeArea_mm2: 36; SizeX_mm: 6; SizeZ_mm: 8.5; AEC Category: Q200; Green_Lifecycle: Active; Green_REACh: Passed
LOGO?#3 = IEC_HighVoltage: as LOGO?#1 on sheet TIDA-01495_Block_Diagram
LOGO?#4 = IEC_HotSurface: as LOGO?#2 on sheet TIDA-01495_Block_Diagram
Q1 Q12 = IPP60R190P6: MOSFET, N-CH, 650 V, 20.2 A, TO-220AB; Manufacturer: Infineon Technologies; Alternate Manufacturer: None; U/M: EA; ChType: N; Value: 650V; VdsMax_V: 650; Value1: ? ohm; Value2: 37 nC; QgTyp_nC: 37; Vgs_V: 20; IdsMax_A: 20.2; SizeAreaWB_mm2: 79.3; SizeArea_mm2: 45.9; SizeX_mm: 10.2; SizeY_mm: 4.5; SizeZ_mm: 19.4; AEC Category: Q101
Q4 = BC848CLT1G, ON Semiconductor: Transistor, NPN, 30 V, 0.1 A, SOT-23; CompType: BJT; PNP: 0; NPN: 1; Vceo_V: 30; Vcesat1_V: 0.7; Value: 30 V; IcRated_A: 0.1; Value1: 0.1 A; HfeMax: 800; TaMin_C: -55; TaMax_C: 150; U/M: EA
Q10 = STB23NM50N: MOSFET N CH 650V 35A D2PAK; Manufacturer: ST Microelectronics; Alternate Manufacturer: None; U/M: EA; VdsMax_V: 650; Value1: ? ohm; Value2: 45 nC; QgTyp_nC: 45; Vgs_V: 25; IdsMax_A: 17
R4 R5 R18 = CRCW080518R2FKEA: RES, 18.2, 1%, 0.125 W, 0805; Manufacturer: Vishay-Dale; CompType: Resistor; Value: 18.2; Value_Code: 18R2; Tolerance_%: 1; Power_W: 0.125; Value2: 0.125W; VDC_V: 150; TempCo: 100 ppm/C; SizeArea_mm2: 2.5; SizeX_mm: 2; SizeY_mm: 1.25; SizeZ_mm: 1.45; EIA_Code: E96; U/M: EA; AEC Category: Q200
R6 R19 R74 = CRCW080510K0FKEA: RES, 10.0 k, 1%, 0.125 W, 0805; Manufacturer: Vishay-Dale; CompType: Resistor; Value: 10.0k; Res_ohm: 10000; Value_Code: 10k0; Tolerance_%: 1; Power_W: 0.125; Value2: 0.125W; VDC_V: 150; TempCo: 100 ppm/C; EIA_Code: E96; U/M: EA
R7 R8 = CSRN2512FK30L0: RES, 0.03, 1%, 2 W, 2512; Manufacturer: Stackpole Electronics Inc; CompType: Resistor; Value: 0.03; Value_Code: R030; Tolerance_%: 1; Power_W: 2; Value2: 2W; TempCo: 200 ppm/C; SizeArea_mm2: 20.16; SizeX_mm: 6.3; SizeY_mm: 3.2; SizeZ_mm: 0.71; EIA_Code: E96; U/M: EA; AEC Category: Q200
R11 R77 = CRCW1206511KFKEA: RES, 511k ohm, 1%, 0.25W, 1206; Manufacturer: Vishay-Dale; CompType: Resistor; Res_ohm: 511000; Tolerance_%: 1; Power_W: 0.25; VDC_V: 200; TempCo: 100 ppm/C; EIA_Code: E96; U/M: EA
R14 R76 = CRCW120649K9FKEA: RES, 49.9k ohm, 1%, 0.25W, 1206; Manufacturer: Vishay-Dale; CompType: Resistor; Res_ohm: 49900; Value_Code: 49k9; Tolerance_%: 1; Power_W: 0.25; VDC_V: 200; TempCo: 100 ppm/C; EIA_Code: E96; U/M: EA
R15 R16 = CRCW08052R20JNEA: RES, 2.2, 5%, 0.125 W, 0805; Manufacturer: Vishay-Dale; CompType: Resistor; Value: 2.2; Value_Code: 2R20; Tolerance_%: 5; Power_W: 0.125; Value2: 0.125W; VDC_V: 150; TempCo: 200 ppm/C; SizeArea_mm2: 2.5; SizeX_mm: 2; SizeY_mm: 1.25; SizeZ_mm: 1.45; EIA_Code: E24; U/M: EA; AEC Category: Q200; Green_Lifecycle: Active; Green_REACh: Passed
R20 = CRCW08053M01FKEA: RES, 3.01 M, 1%, 0.125 W, 0805; Manufacturer: Vishay-Dale; CompType: Resistor; Value: 3.01Meg; Res_ohm: 3010000; Value_Code: 3M01; Tolerance_%: 1; Power_W: 0.125; Value2: 0.125W; VDC_V: 150; TempCo: 100 ppm/C; EIA_Code: E96; U/M: EA
R21 R23 R33 = CRCW08052M87FKEA: RES, 2.87 M, 1%, 0.125 W, 0805; Manufacturer: Vishay-Dale; CompType: Resistor; Value: 2.87Meg; Res_ohm: 2870000; Value_Code: 2M87; Tolerance_%: 1; Power_W: 0.125; Value2: 0.125W; VDC_V: 150; TempCo: 100 ppm/C; EIA_Code: E96; U/M: EA
R24 R26 = CRCW060316K5FKEA: RES, 16.5 k, 1%, 0.1 W, 0603; Manufacturer: Vishay-Dale; CompType: Resistor; Value: 16.5k; Res_ohm: 16500; Value_Code: 16k5; Tolerance_%: 1; Power_W: 0.1; Value2: 0.1W; VDC_V: 75; TempCo: 100 ppm/C; EIA_Code: E96; U/M: EA
R27 R34 R46 R86 R87 = CRCW08052M74FKEA: RES, 2.74 M, 1%, 0.125 W, 0805; Manufacturer: Vishay-Dale; CompType: Resistor; Value: 2.74Meg; Res_ohm: 2740000; Value_Code: 2M74; Tolerance_%: 1; Power_W: 0.125; Value2: 0.125W; VDC_V: 150; TempCo: 100 ppm/C; EIA_Code: E96; U/M: EA
R28 = CRCW06032K20JNEA: RES, 2.2 k, 5%, 0.1 W, 0603; Manufacturer: Vishay-Dale; CompType: Resistor; Value: 2.2k; Res_ohm: 2200; Value_Code: 2k20; Tolerance_%: 5; Power_W: 0.1; Value2: 0.1W; VDC_V: 75; TempCo: 200 ppm/C; EIA_Code: E24; U/M: EA
R30 = CRCW0603100RFKEA: RES, 100, 1%, 0.1 W, 0603; Manufacturer: Vishay-Dale; CompType: Resistor; Value: 100; Value_Code: 100R; Tolerance_%: 1; Power_W: 0.1; Value2: 0.1W; VDC_V: 75; TempCo: 100 ppm/C; EIA_Code: E96; U/M: EA
R35 R88 = CRCW0603133KFKEA: RES, 133 k, 1%, 0.1 W, 0603; Manufacturer: Vishay-Dale; CompType: Resistor; Value: 133k; Res_ohm: 133000; Tolerance_%: 1; Power_W: 0.1; Value2: 0.1W; VDC_V: 75; TempCo: 100 ppm/C; EIA_Code: E96; U/M: EA
R37 R39 R41 R51 R62 = CRCW0603100KJNEA: RES, 100 k, 5%, 0.1 W, 0603; Manufacturer: Vishay-Dale; CompType: Resistor; Value: 100k; Res_ohm: 100000; Tolerance_%: 5; Power_W: 0.1; Value2: 0.1W; VDC_V: 75; TempCo: 200 ppm/C; EIA_Code: E24; U/M: EA
R42 = CRCW06037K50FKEA: RES, 7.50 k, 1%, 0.1 W, 0603; Manufacturer: Vishay-Dale; CompType: Resistor; Value: 7.50k; Res_ohm: 7500; Value_Code: 7k50; Tolerance_%: 1; Power_W: 0.1; Value2: 0.1W; VDC_V: 75; TempCo: 100 ppm/C; EIA_Code: E96; U/M: EA
R55 = CRCW060312K0JNEA: RES, 12 k, 5%, 0.1 W, 0603; Manufacturer: Vishay-Dale; CompType: Resistor; Value: 12k; Res_ohm: 12000; Value_Code: 12k0; Tolerance_%: 5; Power_W: 0.1; Value2: 0.1W; VDC_V: 75; TempCo: 200 ppm/C; EIA_Code: E24; U/M: EA
R56 = RT0603BRD0747KL: RES, 47.0 k, 0.1%, 0.1 W, 0603; Manufacturer: Yageo America; CompType: Resistor; Value: 47.0k; Res_ohm: 47000; Value_Code: 47k0; Tolerance_%: 0.1; Value2: 0.1W; VDC_V: 75; TempCo: 25 ppm/C; EIA_Code: E192; U/M: EA
R58 R59 = CRCW060310R0FKEAHP: RES, 10.0, 1%, 0.25 W, 0603; Manufacturer: Vishay-Dale; CompType: Resistor; Value: 10.0; Res_ohm: 10; Value_Code: 10R0; Tolerance_%: 1; Power_W: 0.25; Value2: 0.25W; VDC_V: 75; TempCo: 100 ppm/C; SizeArea_mm2: 1.28; SizeX_mm: 1.6; SizeY_mm: 0.8; EIA_Code: E96; U/M: EA; AEC Category: Q200; Green_Lifecycle: Active; Green_REACh: Passed
R75 = CMP-0022142-4: RES, 1.10 M, 1%, 0.1 W, AEC-Q200 Grade 0, 0603; Manufacturer: Vishay-Dale; Power_W: 100mW; TempCo: 100 ppm/C; Value_Code: 1M10; Value: 1.10Meg; EIA_Code: E96; Res_ohm: 1.1M; SizeX_mm: 1.6; SizeY_mm: 0.8; SizeZ_mm: 1; Value2: 0.1W; SizeArea_mm2: 1.28; AEC Qualified: Y; VDC_V: 75V; AEC Category: Q200; AEC Grade: 0
R89 = CRCW060366K5FKEA: RES, 66.5 k, 1%, 0.1 W, 0603; Manufacturer: Vishay-Dale; CompType: Resistor; Value: 66.5k; Res_ohm: 66500; Value_Code: 66k5; Tolerance_%: 1; Power_W: 0.1; Value2: 0.1W; VDC_V: 75; TempCo: 100 ppm/C; EIA_Code: E96; U/M: EA
R90 = CRCW060382K5FKEA: RES, 82.5 k, 1%, 0.1 W, 0603; Manufacturer: Vishay-Dale; CompType: Resistor; Value: 82.5k; Res_ohm: 82500; Value_Code: 82k5; Tolerance_%: 1; Power_W: 0.1; Value2: 0.1W; VDC_V: 75; TempCo: 100 ppm/C; EIA_Code: E96; U/M: EA
RT1 = B57236S0100M000: Thermistor NTC, 10 ohm, 20%, Disc_11.5mmx6mm; Manufacturer: EPCOS Inc; Tolerance_%: 20; Power_W: 2.1; TaMin_C: -55; TaMax_C: 170; U/M: EA
RV1 = S10K275E2: Varistor 275V RMS 10MM Radial, TH; Manufacturer: EPCOS Inc; SymbolCreator: a0412235
TP2 = 5000: Test Point, Miniature, Red, TH; Manufacturer: Keystone; CompType: Test Point Loop; U/M: EA
TP3 = 5001: Test Point, Miniature, Black, TH; Manufacturer: Keystone; CompType: Test Point Loop; U/M: EA
U1 = UCC27524AD: Dual 5-A High-Speed Low-Side Gate Driver, D0008A; Manufacturer: Texas Instruments; SymbolCreator: a0411947; CompType: IC; U/M: EA
U3 = UCC28063DR: Natural Interleaving™ Transition-Mode PFC Controller with Improved Audible Noise Immunity, D0016A; Manufacturer: Texas Instruments; SymbolCreator: Altium; CompType: IC; U/M: EA
U4 = UCC28880DR: 700-V Lowest Quiescent Current Off-Line Switcher, D0007A; Manufacturer: Texas Instruments; SymbolCreator: a0411947; CompType: IC; U/M: EA
U13 = CMP-0073526-1: 36V, Low-Power, RRO, General-Purpose Operational Amplifier, DBV0005A (SOT-23-5); Alternate PartNumber: TLV171IDBVT; Alternate Manufacturer: Texas Instruments; SizeAreaWB_mm2: 14.82; U/M: EA; SizeZ_mm: 1.45; SizeX_mm: 2.8; SizeY_mm: 2.9; SizeArea_mm2: 8.12; CompType: IC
